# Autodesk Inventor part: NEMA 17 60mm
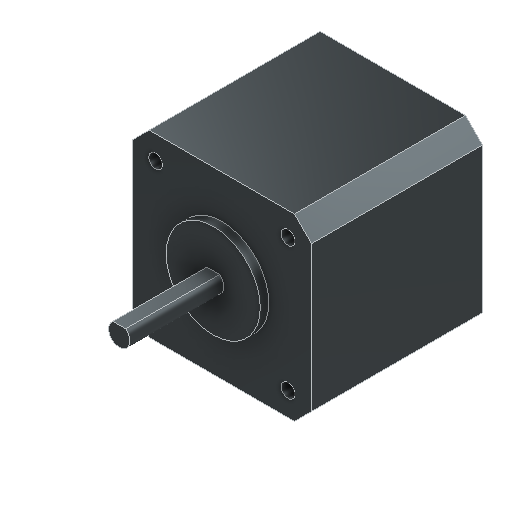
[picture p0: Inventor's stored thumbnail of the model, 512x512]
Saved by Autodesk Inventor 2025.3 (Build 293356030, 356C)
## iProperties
Created: 2026-03
Part Number: NEMA 17 60mm
Material: Generico
Description: NEMA 17
Document SubType Name: Modeling
Designer: R5800u
Density: 1 g/cm^3
Appearance: Grigio ferro
Author: R5800u
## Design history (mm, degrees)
node "NEMA 17"
sketch "Schizzo1"
  geometry: L1 (-2.707, 42)-(39.293, 42); L2 (39.293, 42)-(39.293, 0); L3 (39.293, 0)-(-2.707, 0); L4 (-2.707, 0)-(-2.707, 42); L5 (-2.707, 42)-(39.293, 0); L6 (39.293, 42)-(-2.707, 0); L7 (50.204, 58.756)-(-13.618, 58.756); L8 (-13.618, 58.756)-(-13.618, -16.756); L9 (-13.618, -16.756)-(50.204, -16.756); L10 (50.204, -16.756)-(50.204, 58.756); L11 (50.204, 58.756)-(-13.618, -16.756); L12 (-13.618, 58.756)-(50.204, -16.756); A1 r 2.5 centre (18.293, 21) between (16.793, 23) and (19.793, 23) reference; 1 further point
  constraints: 24 end point, 4 midpoint, 4 parallel, 2 horizontal, 2 perpendicular
  dimensions: "d0" = 42 distance of L2.end L3.end; "d1" = 42 distance of L1.end L2.end
extrude "Estrusione1" cut sketch "Schizzo1" extent not by distance; stored distance "d2" = 0; taper "d3" = 0 deg
sketch "Schizzo2"
  geometry: L1 (1.5, 2)-(-1.5, 2) reference; A1 r 2.5 centre (0, 0) between (-1.5, 2) and (1.5, 2) reference; 1 further point
extrude "Estrusione2" cut sketch "Schizzo2" distance "d4" = 1; taper "d5" = 0 deg
chamfer "Smusso1" distance "d6" = 4; stored, may be unused: second distance "d7" = 2, angle "d8" = 45 deg
sketch "Schizzo3"
  geometry: L1 (38, -38)-(34, -42) reference; L2 (38, -38)-(38, -4) reference; L3 (34, 0)-(38, -4) reference; L4 (34, 0)-(0, 0) reference; L5 (-4, -4)-(0, 0) reference; L6 (-4, -4)-(-4, -38) reference; L7 (0, -42)-(-4, -38) reference; L8 (0, -42)-(34, -42) reference; C1 r 1.6 at (1.5, -5.5) reference; C2 r 1.6 at (1.5, -36.5) reference; C3 r 1.6 at (32.5, -36.5) reference; C4 r 1.6 at (32.5, -5.5) reference; 1 further point
extrude "Estrusione3" join sketch "Schizzo3" distance "d9" = 2; taper "d10" = 0 deg
node "Solido1"
node "Linea chiusa proiettata1"
node "Linea chiusa proiettata2"
